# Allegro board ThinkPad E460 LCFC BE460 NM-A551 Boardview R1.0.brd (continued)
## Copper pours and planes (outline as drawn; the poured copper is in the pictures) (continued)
DH_1.35V on BOTTOM (solid shape): 171.44,171.36 171.44,170.61 171.34,170.51 171.34,170.51 170.55,170.51 170.45,170.41 169.87,170.41 169.74,170.53 169.74,171.25 169.92,171.43 171.37,171.43
DH_1.35V on IN3 (solid shape): 178.18,170.99 178.18,170.69 178.09,170.59 177.43,170.59 177.05,170.98 177.05,171.35 177.17,171.47 177.69,171.47
DH_CHG on TOP (solid shape): 229.86,115.37 229.86,114.28 229.63,114.05 229.03,114.05 228.73,114.35 228.73,115.34 228.96,115.58 229.65,115.58
DH_CHG on BOTTOM (solid shape): 230.14,115.63 230.14,114.72 229.55,114.13 228.84,114.13 228.62,114.36 228.62,115.37 229.03,115.78 229.98,115.78
DH_CHG on BOTTOM (solid shape): 223.29,111.4 223.43,111.26 223.43,111.04 223.29,110.9 222.37,110.9 222.13,111.14 221.81,111.14 221.79,111.16 221.03,111.16 221.03,111.32 221.09,111.38 221.8,111.38 221.82,111.4 223.15,111.4
DH_CHG on IN3 (solid shape): 223.77,111.84 223.77,111 223.69,110.91 222.35,110.91 222.25,111.02 222.25,111.51 222.61,111.87 223.74,111.87
DH_CHG on IN3 (solid shape): 229.52,115.26 229.52,114.43 229.32,114.22 229.18,114.22 228.59,113.63 228.5,113.63 227.93,114.2 227.93,114.44 228.9,115.41 229.37,115.41
DL_1.35V on TOP (solid shape): 170.97,175.34 170.97,175.01 170.77,174.82 169.71,174.82 169.54,174.99 169.54,175.3 169.76,175.52 170.78,175.52
DL_1.35V on TOP (solid shape): 179.88,172.13 179.88,171.41 179.78,171.31 179.7,171.31 179.62,171.39 179.62,171.49 178.38,172.73 178.38,172.94 178.54,173.11 178.91,173.11
DL_1.35V on BOTTOM (solid shape): 170.8,175.69 170.8,174.84 170.7,174.74 169.23,174.74 169.1,174.87 169.1,175.58 169.25,175.73 170.77,175.73
DL_1.35V on BOTTOM (solid shape): 179.44,172.46 179.44,172.18 179.3,172.04 179.01,172.04 178.36,172.69 178.36,172.96 178.49,173.09 178.8,173.09
DL_1.35V on IN3 (solid shape): 178.81,173.33 178.81,173.13 179.41,172.52 179.41,172.13 179.34,172.06 179.04,172.06 178.26,172.84 178.22,172.84 178.01,173.06 178.01,173.29 178.31,173.6 178.54,173.6
DL_CHG on TOP (solid shape): 236.83,118.53 236.83,117.48 236.69,117.33 236,117.33 235.86,117.47 235.86,118.39 236.09,118.62 236.74,118.62
DL_CHG on BOTTOM (solid shape): 236.76,118.38 236.76,117.57 236.63,117.44 235.6,117.44 235.52,117.52 235.52,118.39 235.63,118.5 236.64,118.5
DL_CHG on BOTTOM (solid shape): 223.2,113.22 223.2,113.01 222.54,112.35 221.79,112.35 221.78,112.35 221.02,112.35 221.01,112.36 221.01,112.56 221.82,112.56 221.87,112.62 221.98,112.62 222.71,113.35 223.07,113.35
DL_CHG on IN3 (solid shape): 223.49,113.65 223.49,113.09 222.83,112.43 222.14,112.43 222,112.57 222,113.19 222.7,113.89 223.26,113.89
DL_CHG on IN3 (solid shape): 236.75,118.12 236.75,117.45 236.64,117.34 235.56,117.34 235.43,117.47 235.43,118.42 235.47,118.47 235.69,118.47 235.76,118.54 236.33,118.54
DOCK_ID on TOP (solid shape): 277.19,107.94 277.19,106.88 277.01,106.71 277.01,105.88 277.23,105.66 277.23,105.65 278.43,105.65 278.81,106.04 285.88,106.04 286.01,105.91 286.01,103.68 285.72,103.39 283.08,103.39 281.93,104.53 279.15,104.53 278.6,105.09 276.79,105.09 276.03,105.85 276.03,106.61 275.84,106.8 275.68,106.8 275.25,107.24 275.25,107.99 275.4,108.14 276.99,108.14
EC_SMCA on BOTTOM (solid shape): 249.59,125.07 249.59,122.9 249.76,122.73 249.86,122.73 250.2,122.39 250.2,122.11 249.68,121.59 249.68,120.2 249.46,119.98 249.06,119.98 248.86,120.19 248.86,124.97 249.05,125.16 249.51,125.16
EC_SMDA on BOTTOM (solid shape): 250.56,125.39 251.01,125.39 251.22,125.18 251.22,120.21 251.04,120.03 250.55,120.03 250.39,120.19 250.39,122.17 250.4,122.26 250.39,122.35 250.39,122.49 250.03,122.85 249.99,122.85 249.78,123.06 249.78,125.36 249.77,125.37 249.97,125.57 250.38,125.57
EN_1.8VSP on BOTTOM (solid shape): 186.3,175.87 186.3,175.69 186.3,175.69 186.3,175.28 186.58,175 187.95,175 188.21,174.75 188.21,173.96 188.1,173.86 186.54,173.86 186.17,174.22 186.17,174.6 185.59,175.18 184.73,175.18 184.6,175.31 184.6,175.89 184.68,175.97 186.2,175.97
FB_1.35V on TOP (solid shape): 182.89,169.29 182.89,167.3 182.69,167.1 182.41,167.1 182.18,167.33 182.18,168.85 181.71,169.32 181.7,169.32 181.62,169.4 181.62,169.48 181.71,169.58 182.6,169.58
HG_1PH on BOTTOM (solid shape): 70.78,102.49 70.78,101.6 70.52,101.35 69.74,101.35 69.63,101.45 69.63,102.39 69.82,102.59 70.68,102.59
HG_1PH on BOTTOM (solid shape): 74.41,101.4 74.41,100.94 74.22,100.75 73.89,100.75 73.89,100.93 73.66,101.16 72.94,101.16 72.8,101.31 72.8,101.65 72.87,101.72 74.08,101.72
HG_1PH on IN3 (solid shape): 74.08,101.68 74.08,101.33 73.97,101.22 72.96,101.22 72.88,101.3 72.88,101.67 72.75,101.8 72.75,102.38 72.85,102.48 73.29,102.48
HG_A1 on BOTTOM (solid shape): 67.43,72.34 67.43,71.86 67.18,71.61 66.07,71.61 65.79,71.89 65.79,72.29 65.89,72.39 67.37,72.39
HG_A1 on BOTTOM (solid shape): 75.05,74.43 75.05,73.34 74.96,73.24 73.64,73.24 73.54,73.34 73.54,74.46 73.61,74.54 74.95,74.54
HG_B1 on TOP (solid shape): 82.97,53.53 82.97,52.57 82.95,52.57 82.95,51.87 82.91,51.84 82.62,51.84 82.34,52.11 82.34,53.48 82.55,53.69 82.81,53.69
HG_B1 on BOTTOM (solid shape): 84.29,54.38 84.29,54.11 83.38,53.2 83.38,52.69 83.17,52.48 82.53,52.48 82.23,52.78 82.23,53.33 82.99,54.09 82.99,54.41 83.27,54.7 83.97,54.7
HGNDA on TOP (solid shape): 183.65,57.39 183.68,57.36 185.04,57.36 185.04,57.35 185.04,57.21 185,57.17 183.46,57.17 182.96,57.66 181.85,57.66 180.98,56.8 180.98,56.24 180.93,56.19 180.31,56.19 180.18,56.3 180.02,56.34 179.79,56.34 179.61,56.52 179.61,57.28 179.62,57.3 179.62,57.5 179.79,57.66 181.13,57.66 181.72,58.25 182.79,58.25
HGNDA on TOP: 139.37,55.84 139.95,55.84 140.21,55.59 140.21,51.35 140.38,51.17 140.38,50.71 140.39,50.7 140.39,50.45 140.39,50.12 140.24,49.96 139.3,49.96 139.16,50.1 139.16,55.63
HGNDA on IN1: 137.66,57.56 141.1,57.56 142.23,56.43 142.23,52.37 143.52,51.09 143.63,51.09 144.25,50.47 159.63,50.47 160.01,50.08 174.11,50.08 174.74,50.72 178.43,50.72 178.94,51.23 178.94,52.37 178.55,52.75 176.89,52.75 176.77,52.88 176.77,53.6 179.18,56.01 179.18,57.92 179.71,58.45 180.12,58.45 180.47,58.81 182.23,58.81 183.65,57.39 183.65,49.03 182.63,48.01 137.45,48.01 137.03,48.43 137.03,56.93
HGNDB on TOP (solid shape): 183.41,56.96 184.83,56.96 184.84,56.96 185,56.96 185.03,56.93 185.03,56.79 184.98,56.74 183.44,56.74 183.14,56.45 181.87,56.45 181.86,56.46 181.32,56.46 181.29,56.5 181.29,56.88 181.95,57.54 182.84,57.54
HGNDB on TOP: 138.84,51.54 138.82,51.53 138.82,50.12 138.64,49.94 137.65,49.94 137.57,50.02 137.57,55.4 137.94,55.77 138.78,55.77 138.84,55.72
HGNDB on IN2: 142.36,52.37 144.52,50.21 174.11,50.21 174.62,50.72 178.43,50.72 178.94,51.23 178.94,52.37 178.55,52.75 176.89,52.75 176.77,52.88 176.77,55.51 179.71,58.45 180.12,58.45 180.47,58.81 182.23,58.81 183.65,57.39 183.65,49.03 182.63,48.01 136.76,48.01 136.67,48.1 136.67,55.09 137.05,55.47 137.05,57.5 137.36,57.81 141.12,57.81 142.36,56.56
LANGND on TOP: 287.66,89.18 294.77,89.18 295.13,88.82 295.13,88.04 290.68,88.04 290.3,88.42 289.29,88.42 288.73,87.87 288.73,87.8 288.66,87.8 287.65,86.79 286.89,86.79 286.5,86.41 286.5,72.43 289.37,69.57 290.25,69.57 290.76,70.08 296.14,70.08 296.14,69.27 295.61,68.74 284.6,68.74 284.22,69.12 284.22,70.53 276.09,78.66 273.04,78.66 271.26,80.44 267.07,80.44 264.66,82.85 264.66,83.23 264.28,83.61 263.52,83.61 263.14,83.23 258.95,83.23 258.56,83.61 258.56,86.15 259.71,87.3 259.71,89.84 260.34,90.47 262.25,90.47 262.88,89.84 262.88,87.55 263.01,87.42 277.87,87.42 277.87,89.2 280.28,91.61 280.28,92.5 280.66,92.88 283.96,92.88
LANGND on BOTTOM: 260.08,82.85 259.95,82.72 257.42,82.72 257.17,82.98 257.17,85.9 257.42,86.15 258.69,86.15 258.95,85.9 258.95,85.19 259.28,84.86 259.91,84.86 260.08,84.69
LANGND on BOTTOM: 260.33,90.46 262.24,90.46 262.88,89.81 262.88,87.68 263.01,87.55 277.74,87.55 278,87.3 278,85.9 277.74,85.64 263.38,85.64 260.85,88.17 259.98,88.17 259.71,88.44 259.71,89.83
LANGND on BOTTOM: 284.6,68.88 284.22,69.26 284.22,70.53 277.87,76.88 277.87,78.02 280.03,80.18 280.03,84.76 280.41,85.14 282.06,85.14 282.44,85.52 282.44,86.53 282.69,86.79 284.73,86.79 285.62,87.68 285.62,88.95 285.11,89.45 280.54,89.45 280.28,89.71 280.28,92.5 280.66,92.88 283.96,92.88 287.27,89.58 288.3,89.58 288.41,89.69 294.79,89.69 294.98,89.5 294.98,88.1 294.94,88.06 294.94,88.04 290.81,88.04 290.43,88.42 288.03,88.42 286,86.39 286,80.18 282.31,76.5 282.31,74.85 282.82,74.34 285.87,74.34 286.38,73.83 286.38,73.58 286.25,73.45 286.25,72.56 289.43,69.39 289.43,69.13 289.17,68.88
LANGND on GND1: 284.7,68.75 284.22,69.24 284.22,70.51 276.07,78.66 273.02,78.66 271.24,80.44 267.05,80.44 264.66,82.83 264.66,83.21 264.26,83.61 263.54,83.61 263.16,83.23 258.92,83.23 258.56,83.59 258.56,86.17 259.71,87.32 259.71,89.86 260.32,90.47 262.27,90.47 262.99,89.75 262.99,87.55 277.83,87.55 277.83,89.19 277.85,89.2 280.28,91.64 280.28,92.52 280.64,92.88 284.11,92.88 287.8,89.2 296.56,89.2 297.05,88.71 297.05,87.93 290.7,87.93 290.54,88.08 290.48,88.14 290.19,88.44 289.3,88.44 287.65,86.79 286.89,86.79 286.5,86.41 286.5,72.44 289.43,69.52 290.19,69.52 290.7,70.02 296.13,70.02 296.13,70.09 297.05,70.09 297.05,69.24 296.56,68.75
LANGND on IN1: 284.7,68.75 284.22,69.24 284.22,70.51 276.07,78.66 273.02,78.66 271.75,79.93 266.8,79.93 264,82.72 259.44,82.72 258.55,83.61 258.55,86.16 259.71,87.32 259.71,89.86 260.32,90.47 262.27,90.47 262.96,89.78 262.96,87.55 263.08,87.42 277.87,87.42 277.87,89.2 280.28,91.61 280.28,92.5 280.66,92.88 283.96,92.88 284.73,92.12 284.88,92.12 287.8,89.2 296.56,89.2 297.05,88.71 297.05,87.93 290.7,87.93 290.54,88.08 290.48,88.14 290.19,88.44 289.3,88.44 287.65,86.79 286.89,86.79 286.5,86.41 286.5,72.44 289.43,69.52 290.19,69.52 290.7,70.02 296.13,70.02 296.13,70.09 297.05,70.09 297.05,69.24 296.56,68.75 ; 1 cut-out
LANGND on IN2: 284.7,68.75 284.22,69.24 284.22,70.51 276.07,78.66 273.02,78.66 271.75,79.93 266.8,79.93 264,82.72 258.29,82.72 257.42,83.59 257.42,85.54 257.91,86.03 258.42,86.03 259.71,87.32 259.71,89.86 260.32,90.47 262.27,90.47 262.96,89.78 262.96,87.47 263.01,87.42 277.74,87.42 277.87,87.55 277.87,89.2 280.28,91.61 280.28,92.5 280.66,92.88 284.09,92.88 284.85,92.12 284.88,92.12 287.8,89.2 296.56,89.2 297.05,88.71 297.05,87.93 290.7,87.93 290.54,88.08 290.48,88.14 290.19,88.44 289.3,88.44 287.65,86.79 286.89,86.79 286.5,86.41 286.5,72.44 289.43,69.52 290.19,69.52 290.7,70.02 296.13,70.02 296.13,70.09 297.05,70.09 297.05,69.24 296.56,68.75
LANGND on VCC, GND2: 284.7,68.75 284.22,69.24 284.22,70.51 276.07,78.66 273.02,78.66 271.75,79.93 266.8,79.93 264,82.72 258.29,82.72 257.42,83.59 257.42,85.54 257.91,86.03 258.42,86.03 259.71,87.32 259.71,89.86 260.32,90.47 262.27,90.47 262.99,89.75 262.99,87.55 277.83,87.55 277.83,89.19 277.85,89.2 280.28,91.64 280.28,92.52 280.64,92.88 284.11,92.88 287.8,89.2 296.56,89.2 297.05,88.71 297.05,87.93 290.7,87.93 290.54,88.08 290.48,88.14 290.19,88.44 289.3,88.44 287.65,86.79 286.89,86.79 286.5,86.41 286.5,72.44 289.43,69.52 290.19,69.52 290.7,70.02 296.13,70.02 296.13,70.09 297.05,70.09 297.05,69.24 296.56,68.75
LANGND on IN3: 284.7,68.75 284.22,69.24 284.22,70.51 276.07,78.66 273.02,78.66 271.75,79.93 266.8,79.93 264,82.72 258.29,82.72 257.42,83.59 257.42,85.54 257.91,86.03 258.42,86.03 259.71,87.32 259.71,89.86 260.32,90.47 262.27,90.47 262.96,89.78 262.96,87.42 277.61,87.42 277.87,87.68 277.87,89.2 280.28,91.61 280.28,92.5 280.66,92.88 284.11,92.88 287.8,89.2 296.56,89.2 297.05,88.71 297.05,87.93 290.7,87.93 290.54,88.08 290.48,88.14 290.19,88.44 289.3,88.44 287.65,86.79 286.89,86.79 286.5,86.41 286.5,83.97 282.19,83.97 282.01,83.79 282.01,82.22 283.66,80.56 275.71,80.56 275.46,80.31 275.46,80.26 281.35,74.37 285.92,74.37 286.5,73.78 286.5,72.44 289.43,69.52 290.19,69.52 290.7,70.02 296.13,70.02 296.13,70.09 297.05,70.09 297.05,69.24 296.56,68.75 ; 2 cut-outs
LG_1PH on BOTTOM (solid shape): 63.95,102.22 63.95,101.72 63.83,101.59 63.03,101.59 62.99,101.63 62.99,101.8 62.55,102.24 62.55,102.5 62.68,102.63 63.54,102.63
LG_1PH on IN3 (solid shape): 72.82,99.58 73.48,99.58 73.59,99.48 73.59,99.17 73.5,99.08 72.89,99.08 72.73,98.92 72.25,98.92 72.15,99.01 72.15,99.59 72.23,99.68 72.73,99.68
LG_A1 on BOTTOM (solid shape): 63.53,84.68 63.53,83.65 63.38,83.5 62.48,83.5 62.29,83.69 62.29,84.66 62.4,84.77 63.44,84.77
LG_A1 on BOTTOM (solid shape): 63.53,79.14 63.53,78.12 63.38,77.96 62.48,77.96 62.29,78.15 62.29,79.12 62.4,79.23 63.44,79.23
LG_A1 on BOTTOM (solid shape): 64.45,73.4 64.45,72.68 64.61,72.51 64.61,71.92 64.54,71.85 64.28,71.85 63.91,72.22 63.91,73.13 63.87,73.18 63.87,73.42 64.01,73.56 64.28,73.56
LG_A1 on IN3 (solid shape): 63.52,84.73 63.52,78.88 63.39,78.75 62.53,78.75 62.38,78.9 62.38,84.71 62.52,84.85 63.39,84.85
LG_A1 on IN3 (solid shape): 64.85,74.19 64.85,73.94 64.41,73.51 64.41,72.57 64.28,72.45 63.85,72.45 63.72,72.58 63.72,73.91 63.84,74.03 63.84,74.29 63.86,74.32 64.72,74.32
LG_B1 on TOP (solid shape): 88.76,51.53 91.42,51.53 91.51,51.44 91.51,50.48 91.44,50.4 85.16,50.4 85.01,50.56 85.01,51.29 85.24,51.52 87.44,51.52 87.45,51.54 87.45,51.58 87.16,51.87 84.16,51.87 84.13,51.9 84.13,52.27 84.71,52.84 87.45,52.84
LG_B1 on BOTTOM (solid shape): 86.3,51.45 86.3,50.41 86.17,50.28 85.29,50.28 85.04,50.53 85.04,51.39 85.16,51.52 86.24,51.52
LG_B1 on BOTTOM (solid shape): 92.27,51.48 92.27,50.44 92.14,50.3 90.96,50.3 90.88,50.38 90.88,51.39 91.04,51.54 92.21,51.54
LX_1.35V on TOP (solid shape): 168.59,172.57 168.59,171.5 168.41,171.32 165.82,171.32 165.67,171.47 165.67,172.63 165.86,172.81 168.35,172.81
LX_1.35V on TOP (solid shape): 178.09,173.54 178.09,172.69 179.54,171.25 179.54,171.03 179.47,170.96 178.63,170.96 177.83,171.76 177.27,171.76 177.05,171.97 177.05,173.71 177.22,173.88 177.76,173.88
LX_1.35V on BOTTOM (solid shape): 166,174.7 166,174.7 166.13,174.56 166.14,174.56 166.23,174.46 169.74,174.46 169.99,174.22 169.99,171.85 169.8,171.65 169.66,171.65 169.66,171.62 169.54,171.5 169.54,170.48 169.41,170.35 166.77,170.35 166.41,170 166.41,169.19 166.18,168.95 162.52,168.95 162.27,169.2 162.27,175.67 162.56,175.96 164.74,175.96
LX_CHG on TOP (solid shape): 233.52,115.27 233.52,114.09 233.34,113.91 231.74,113.91 231.51,114.13 231.51,114.82 232.11,115.42 233.38,115.42
LX_CHG on BOTTOM (solid shape): 222.3,110.72 223.63,110.72 223.73,110.62 224.71,110.62 224.8,110.53 224.8,109.7 224.77,109.66 222.96,109.66 221.9,110.71 221.86,110.71 221.82,110.75 221.05,110.75 221.03,110.77 221.03,110.92 221.07,110.97 221.81,110.97 221.84,110.99 222.03,110.99
LX_CHG on BOTTOM (solid shape): 236.4,117.05 236.4,114.02 235.7,113.31 235.7,104.7 235.25,104.25 230.04,104.25 229.98,104.19 229.61,104.19 229.1,104.69 229.1,113.21 230.37,114.48 230.37,115.73 230.52,115.88 231.85,115.88 231.93,115.96 232,115.96 232.71,116.67 232.71,116.74 233.25,117.28 236.18,117.28
LX_CHG on IN3 (solid shape): 232.9,114.37 232.9,113.98 232.67,113.75 232.22,113.75 232.08,113.6 231.67,114.01 231.67,114.49 231.76,114.58 232.69,114.58
LX_CHG on IN3 (solid shape): 224.6,110.03 224.56,110 223.57,110 223.54,110.03 222.6,110.03 222.4,110.24 222.4,110.57 222.54,110.71 223.49,110.71 223.5,110.72 223.98,110.72 224.04,110.77 224.6,110.77
P2 on BOTTOM (solid shape): 272.01,108.22 272.01,107.8 272.78,107.03 273.7,107.03 273.83,106.9 273.83,104.68 273.54,104.39 273.42,104.39 272.97,103.94 272.97,103.19 272.79,103.01 272.13,103.01 272.01,103.13 272.01,103.89 272.2,104.07 272.2,105.05 271.98,105.27 270.65,105.27 270.55,105.38 270.55,108.16 270.83,108.45 271.78,108.45
P3 on BOTTOM (solid shape): 267.71,107.75 270.15,107.75 270.33,107.57 270.33,101.7 270.12,101.49 266.57,101.49 266.41,101.65 266.41,101.85 266.42,101.85 266.42,102.01 266.41,102.01 266.41,103.38 266.06,103.74 263.88,103.74 263.55,104.07 263.55,108.68 263.72,108.85 266.61,108.85
RJ45_GND on BOTTOM: 266.44,81.45 270.12,81.45 270.13,81.45 272.79,81.45 273.42,80.82 277.74,80.82 278.38,81.45 278.38,87.55 279.9,89.07 282.95,89.07 283.2,88.82 283.2,87.17 283.08,87.04 280.28,87.04 279.77,86.53 279.77,80.44 278.12,78.79 273.04,78.79 272.39,79.44 272.17,79.44 272.15,79.42 266.57,79.42 266.06,79.93 266.06,81.07
SPK_L1-_CON on TOP: 190.2,66.4 190.89,66.4 191.01,66.28 191.01,65.21 189.49,63.68 188.86,63.68 188.6,63.43 188.6,62.29 188.45,62.14 187.74,62.14 187.61,62.26 187.61,63.94 188.27,64.6 189.16,64.6 190.13,65.56 190.13,66.33
SPK_L1-_CON on BOTTOM: 239.88,99.09 239.88,97.06 240.27,96.68 241.41,96.68 241.54,96.81 241.54,99.09 241.41,99.22 240.01,99.22
SPK_L1-_CON on IN3: 188.45,64.68 189.85,64.68 190.1,64.42 190.1,63.79 190.61,63.28 190.61,62.39 190.35,62.14 188.45,62.14 188.2,62.39 188.2,64.42
SPK_L2+_CON on TOP: 191.29,66.38 191.85,66.38 191.98,66.25 191.98,64.19 191.04,63.25 191.04,62.34 190.79,62.08 189.85,62.08 189.69,62.24 189.69,63.63 191.22,65.16 191.22,66.3
SPK_L2+_CON on BOTTOM: 238.61,99.22 239.5,99.22 239.63,99.09 239.63,96.93 239.76,96.81 239.76,95.16 239.5,94.9 238.61,94.9 238.49,95.03 238.49,99.09
SPK_L2+_CON on IN3: 190.74,65.82 191.88,65.82 192.01,65.69 192.01,64.04 191.88,63.91 190.74,63.91 190.61,64.04 190.61,65.69
SPK_R1-_CON on TOP: 189.24,66.45 189.8,66.45 189.9,66.35 189.9,65.59 189.08,64.78 188.17,64.78 187.38,63.99 187.38,62.47 187.18,62.26 186.47,62.26 186.37,62.36 186.37,64.19 187.66,65.49 188.93,65.49 189.14,65.69 189.14,66.35
SPK_R1-_CON on BOTTOM: 237.34,99.22 238.11,99.22 238.23,99.09 238.23,96.17 237.98,95.92 236.84,95.92 236.71,96.04 236.71,96.68 237.22,97.19 237.22,99.09
SPK_R1-_CON on IN3: 189.72,65.06 188.2,65.06 187.81,64.68 187.81,63.28 187.56,63.02 186.42,63.02 186.29,63.15 186.29,66.33 186.54,66.58 189.85,66.58 189.97,66.45 189.97,65.31
SPK_R2+_CON on TOP: 188.73,66.55 186.93,66.55 183.8,63.43 183.8,62.49 183.95,62.34 184.89,62.34 185.45,62.9 185.45,63.51 187.64,65.69 188.75,65.69 188.88,65.82 188.88,66.4
SPK_R2+_CON on BOTTOM: 234.68,99.22 236.84,99.22 236.96,99.09 236.96,97.7 236.71,97.44 234.68,97.44 234.55,97.57 234.55,99.09
SPK_R2+_CON on IN3: 185.27,63.28 185.15,63.15 184,63.15 183.88,63.28 183.88,64.8 184,64.93 185.15,64.93 185.27,64.8
SW_1.00VS on TOP (solid shape): 144.28,173.47 144.28,171.56 144.1,171.38 141.98,171.38 141.58,171.77 141.58,173.32 141.85,173.59 144.16,173.59
SW_1.00VS on BOTTOM (solid shape): 145.67,175.56 145.67,175.31 147.22,173.76 148.28,172.7 148.28,170.68 148.25,170.65 147.44,170.65 147.43,170.65 147.17,170.9 146.24,170.9 146.1,171.04 140.08,171.04 139.85,171.27 139.85,173.85 139.01,174.7 139.01,175.61 139.23,175.84 145.39,175.84
SW_1PH on TOP (solid shape): 68.69,103.11 68.69,101.74 68.44,101.49 66.98,101.49 66.84,101.63 66.84,102.89 67.23,103.28 68.52,103.28
SW_1PH on BOTTOM (solid shape): 72.75,100.93 73.48,100.93 73.85,100.56 74.26,100.56 74.3,100.52 74.3,100.25 74.29,100.24 73.46,100.24 73.29,100.4 71.21,100.4 71.02,100.59 71.02,101.16 71.21,101.36 72.32,101.36
SW_1PH on BOTTOM (solid shape): 68.67,109.53 68.67,107.02 68.24,106.59 67.11,106.59 67.07,106.55 67.07,105.9 68.14,105.9 68.3,105.73 68.56,105.73 69.39,104.91 69.39,101.44 68.95,101 67.79,101 67.45,100.66 67.45,99.53 67.03,99.11 64.65,99.11 64.23,99.53 64.23,102.2 63.86,102.57 63.86,108.24 65.42,109.8 68.4,109.8
SW_1PH on IN3 (solid shape): 68.75,102.76 68.75,102.51 68.4,102.17 68.2,102.17 67.83,102.54 67.51,102.54 67.34,102.71 67.34,103.06 67.43,103.15 68.36,103.15
SW_A1 on TOP (solid shape): 67.85,74.41 67.85,73.75 67.67,73.57 67.2,73.57 67.18,73.59 65.2,73.59 65.09,73.69 65.09,74.33 65.28,74.52 67.74,74.52
SW_A1 on BOTTOM (solid shape): 69.22,83.82 69.22,81.66 71.12,79.76 72.42,79.76 72.64,79.55 72.64,78.3 72.76,78.18 73.65,78.18 73.78,78.3 73.78,79.62 74.21,80.06 74.21,80.07 76.07,80.07 76.22,79.92 76.22,76.62 74.46,74.86 73.33,74.86 72.92,74.45 72.92,73.34 72.78,73.21 69.07,73.21 68.58,72.72 66.96,72.72 66.95,72.73 65.84,72.73 65.6,72.49 65.6,71.86 65.54,71.8 65.41,71.8 65.28,71.94 65.28,72.46 65.25,72.49 65.25,73.21 64.66,73.8 64.66,73.8 64.21,74.25 64.21,83.99 64.68,84.46 68.58,84.46
SW_B1 on TOP (solid shape): 85.32,55.59 85.32,54.15 84.68,53.51 84.02,53.51 83.46,52.95 83.46,51.91 83.41,51.86 83.18,51.86 83.13,51.91 83.13,53.28 83.53,53.69 83.53,54.41 83.54,54.42 83.54,55.56 83.65,55.67 85.24,55.67
SW_B1 on BOTTOM (solid shape): 89.37,62.82 89.37,61.56 90.1,61.56 90.1,62.77 90.55,63.22 93.78,63.22 94.07,62.93 94.07,59.04 96.57,56.54 96.57,54.6 96.8,54.37 97.71,54.37 97.89,54.19 97.89,53.39 97.78,53.27 96.67,53.27 96.57,53.16 96.57,52.13 96.42,51.99 85.33,51.99 84.9,52.41 84.9,54.47 84.41,54.97 83.26,54.97 83.03,55.2 83.03,58.87 86.26,62.1 86.26,63.12 86.44,63.3 88.88,63.3
VGA_LGATE1 on TOP (solid shape): 94.3,163.81 94.3,162.8 94.15,162.65 93.19,162.65 92.99,162.85 92.99,163.69 93.22,163.92 94.18,163.92
VGA_LGATE1 on BOTTOM (solid shape): 100.04,164.63 100.04,163.47 99.89,163.32 99.89,163.32 99.22,162.65 99.14,162.65 98.81,162.97 98.81,163.87 99.65,164.7 99.97,164.7
VGA_LGATE1 on BOTTOM (solid shape): 114.15,170.82 114.74,170.82 114.77,170.8 114.77,170.61 114.75,170.6 114.14,170.6 114.12,170.57 113.53,170.57 113.47,170.52 113.47,170.51 112.9,169.94 112.34,169.94 112.2,170.07 112.2,170.28 112.39,170.48 112.53,170.48 112.9,170.85 114.13,170.85
VGA_LGATE1 on IN3 (solid shape): 100.05,164.52 100.05,163.75 99.88,163.58 99.72,163.58 98.89,162.75 93.24,162.75 93.1,162.89 93.1,163.76 93.23,163.9 98.34,163.9 98.35,163.91 98.84,163.91 99.63,164.7 99.87,164.7
VGA_LGATE1 on IN3 (solid shape): 113.26,170.72 113.26,170.26 112.52,169.52 110.53,169.52 110.41,169.64 110.41,170.39 110.47,170.44 110.81,170.44 110.89,170.36 112.3,170.36 112.4,170.45 112.54,170.45 112.89,170.8 113.18,170.8
VGA_LGATE2 on TOP (solid shape): 98.74,169.23 98.74,168.26 98.5,168.02 97.55,168.02 97.35,168.22 97.35,169.13 97.55,169.33 98.64,169.33
VGA_LGATE2 on BOTTOM (solid shape): 92.83,169.06 92.83,168.11 92.71,168 91.69,168 91.55,168.13 91.55,169.09 91.71,169.26 92.63,169.26
VGA_LGATE2 on BOTTOM (solid shape): 113.04,172.05 114.14,172.05 114.17,172.02 114.75,172.02 114.81,171.96 114.81,171.84 114.78,171.81 114.15,171.81 114.12,171.78 112.03,171.78 111.75,172.06 111.75,172.44 111.91,172.59 112.49,172.59
VGA_LGATE2 on IN3 (solid shape): 98.75,169.09 98.75,168.26 98.59,168.1 91.6,168.1 91.49,168.22 91.49,169.1 91.66,169.27 98.57,169.27
VGA_LGATE2 on IN3 (solid shape): 111.35,172.68 112.04,172.68 112.27,172.45 112.65,172.45 112.89,172.21 112.89,171.94 112.79,171.84 111.38,171.84 111.31,171.76 111.04,171.76 110.9,171.91 110.9,172.7 110.97,172.78 111.25,172.78
VGA_PHASE1 on TOP (solid shape): 101.46,162.37 101.46,158.66 99.97,157.17 90.38,157.17 89.86,157.69 89.86,159.46 90.95,160.55 90.95,161.04 91.48,161.57 93.1,161.57 93.72,162.19 99.02,162.19 99.53,162.69 101.15,162.69
VGA_PHASE1 on BOTTOM (solid shape): 114.16,170.43 114.78,170.43 114.8,170.4 114.8,170.25 114.77,170.21 113.94,170.21 113.07,169.33 112.44,169.33 112.16,169.06 112.16,168.81 111.81,168.45 111.56,168.45 111.56,168.45 109.77,168.45 109.64,168.58 109.64,169.35 110.09,169.8 113.05,169.8 113.69,170.45 114.14,170.45
VGA_PHASE1 on BOTTOM (solid shape): 92.89,163.9 92.89,162.81 93.18,162.52 93.8,162.52 93.97,162.36 99.25,162.36 99.25,162.36 99.46,162.36 99.56,162.46 102.35,162.46 102.72,162.1 102.72,158.69 101.18,157.16 93.77,157.16 93.32,157.61 89.54,157.61 89.07,158.08 89.07,160.75 89.35,161.03 90.48,161.03 90.54,161.09 90.54,161.57 90.53,161.58 90.53,161.86 90.42,161.97 89.27,161.97 89.07,162.17 89.07,164.29 89.35,164.57 92.22,164.57
VGA_PHASE1 on IN3 (solid shape): 112.1,169.07 112.1,168.8 111.93,168.63 111.57,168.63 111.14,168.19 110.83,168.19 110.45,168.57 110.78,168.9 110.82,168.9 111.08,169.16 112.02,169.16
VGA_PHASE1 on IN3 (solid shape): 100.02,162.52 100.02,162.24 99.85,162.07 99.85,161.73 99.91,161.67 99.91,161.47 99.78,161.34 99.27,161.34 99.16,161.45 99.16,162.56 99.33,162.73 99.81,162.73
VGA_PHASE2 on TOP (solid shape): 98.23,174.31 98.23,170.31 97.7,169.77 92.62,169.77 92.3,169.45 90.96,169.45 90.44,169.97 90.44,170.44 90.26,170.63 87.73,170.63 87.24,171.12 87.24,172.67 89.23,174.67 97.88,174.67
VGA_PHASE2 on BOTTOM (solid shape): 113.67,172.45 113.69,172.44 114.08,172.44 114.1,172.42 114.79,172.42 114.79,172.41 114.79,172.23 114.76,172.19 114.14,172.19 114.11,172.17 113.16,172.17 112.45,172.89 110.73,172.89 110.5,173.12 110.5,173.69 110.6,173.79 112.34,173.79
VGA_PHASE2 on BOTTOM (solid shape): 97.56,174.28 97.56,173.89 97.94,173.51 99.08,173.51 99.31,173.28 99.31,170.26 99.31,170.26 99.31,170.12 99.07,169.89 98.07,169.89 97.68,169.5 91.6,169.5 91.3,169.21 91.3,168.17 91.11,167.98 89.72,167.98 89.41,167.67 89.41,167.23 88.46,166.27 86.99,166.27 86.36,166.9 86.36,168.95 86.82,169.41 86.83,169.4 88.1,169.4 88.1,170.01 88,170.11 86.73,170.11 86.36,170.47 86.36,173.07 89,175.71 96.14,175.71
VGA_PHASE2 on IN3 (solid shape): 92.64,174.02 92.64,173.43 92.21,173 91.83,173 91.52,173.32 91.31,173.32 91.12,173.51 91.12,173.7 91.26,173.83 91.56,173.83 91.91,174.18 92.48,174.18
VGA_PHASE2 on IN3 (solid shape): 112.25,173.62 112.55,173.62 112.85,173.32 112.85,173.03 112.77,172.95 112.46,172.95 112.35,173.07 111.81,173.07 111.46,173.41 111.37,173.41 111.24,173.54 111.24,174.14 111.28,174.18 111.69,174.18
VGA_UGATE1 on BOTTOM (solid shape): 102.82,163.79 102.82,163.2 102.29,162.67 101.19,162.67 100.97,162.89 100.97,163.32 101.61,163.96 102.65,163.96
VGA_UGATE1 on BOTTOM (solid shape): 114.8,169.99 114.8,169.83 114.77,169.8 114.14,169.8 113.96,169.63 113.96,169.19 113.32,168.55 112.52,168.55 112.39,168.67 112.39,168.91 112.55,169.07 113.11,169.07 113.76,169.73 114.06,170.02 114.76,170.02
VGA_UGATE1 on IN3 (solid shape): 103.18,163.92 103.18,163.43 103.06,163.31 101.83,163.31 101.68,163.46 101.68,163.75 101.83,163.91 102.45,163.91 102.61,164.06 103.04,164.06
VGA_UGATE1 on IN3 (solid shape): 113.58,169.07 113.58,168.69 113.44,168.55 113.27,168.55 112.81,168.09 112.42,168.09 112.18,168.32 112.18,168.52 112.38,168.71 112.38,168.92 112.59,169.13 113.14,169.13 113.19,169.19 113.46,169.19
VGA_UGATE2 on BOTTOM (solid shape): 99.39,174.9 99.39,174.29 98.87,173.77 97.9,173.77 97.78,173.89 97.78,174.78 97.99,174.99 99.31,174.99
VGA_UGATE2 on BOTTOM (solid shape): 113.85,174.08 113.85,173.09 114.13,172.81 114.78,172.81 114.78,172.62 114.76,172.6 113.79,172.6 113.78,172.59 113.39,172.98 112.35,174.03 112.35,174.29 112.47,174.41 113.52,174.41
VGA_UGATE2 on IN3 (solid shape): 99.95,175.04 99.95,174.51 99.83,174.39 98.34,174.39 98.22,174.51 98.22,174.93 98.42,175.14 99.84,175.14
VMB on BOTTOM (solid shape): 265.19,114.42 265.19,109.36 264.84,109.01 262.18,109.01 262.15,109.04 261.71,109.04 261.61,109.14 261.61,109.65 261.42,109.84 260.63,109.84 260.37,110.1 260.37,112 260.83,112.45 260.83,114.75 261.49,115.41 264.2,115.41
VMB2 on TOP (solid shape): 251.24,117.25 258.41,117.25 259.28,116.38 259.28,112.23 259,111.96 246.05,111.96 245.04,112.96 245.04,114.91 242.72,117.24 242.72,118.84 243.02,119.15 243.05,119.12 243.71,119.12 243.73,119.15 244.68,119.15 245.57,120.03 248.45,120.03
VMB2 on BOTTOM (solid shape): 248.62,125.11 248.62,119.92 249.23,119.31 251.8,119.31 253.2,117.92 254.26,117.92 255.6,116.58 255.6,116.55 256.03,116.11 259.9,116.11 260.37,115.64 260.37,112.74 259.9,112.27 256.06,112.27 255.24,111.46 246.05,111.46 245.42,112.08 245.42,124.93 245.68,125.19 248.54,125.19
VSYSTEM on BOTTOM (solid shape): 277.42,108.04 277.42,105.29 277.29,105.16 277.29,102.21 277.08,102 274.19,102 274.06,102.13 274.06,107.85 273.61,108.3 273.61,108.98 273.78,109.15 276.31,109.15
N18669 on BOTTOM (solid shape): 111.79,168.09 111.79,167.29 111.67,167.17 109.79,167.17 109.53,166.9 108.55,166.9 108.4,167.05 108.4,167.43 109.21,168.24 111.64,168.24
N18705 on BOTTOM (solid shape): 114.8,169.56 114.8,169.32 114.73,169.25 114.73,168.79 113.15,167.21 112.33,167.21 112.24,167.3 112.24,168.15 112.43,168.34 113.32,168.34 114.15,169.17 114.15,169.53 114.23,169.61 114.76,169.61
N22144 on BOTTOM (solid shape): 112.27,175.36 112.27,174.46 112.18,174.37 111.86,174.37 111.85,174.36 110.24,174.36 110.03,174.57 110.03,174.93 109.91,175.05 108.91,175.05 108.83,175.13 108.83,175.43 108.97,175.57 112.06,175.57
N22186 on BOTTOM (solid shape): 114.7,175.35 114.7,173.39 114.8,173.29 114.8,173.08 114.73,173.01 114.2,173.01 113.99,173.22 113.99,174.14 113.57,174.55 112.89,174.55 112.82,174.62 112.82,175.41 112.88,175.46 114.6,175.46
N34928 on BOTTOM (solid shape): 114.78,171.57 114.78,171.45 114.72,171.39 112.31,171.39 112.06,171.14 111.09,171.14 111.02,171.22 111.02,171.52 111.12,171.62 114.72,171.62
N15168718 on TOP (solid shape): 176.82,173.68 176.82,171.62 176.71,171.51 174.58,171.51 174.34,171.75 174.34,173.71 174.47,173.83 175.88,173.83 175.88,173.84 176.66,173.84
N15269244 on BOTTOM (solid shape): 194.05,175.81 194.05,175.26 193.92,175.13 192.77,175.13 192.41,174.77 192.41,173.14 192.4,173.12 191.99,173.12 191.92,173.2 191.92,173.24 191.29,173.86 190.54,173.86 190.44,173.96 190.44,174.15 190.93,174.63 190.93,175.32 191.49,175.89 193.97,175.89
N16794121 on BOTTOM (solid shape): 263.22,108.68 263.22,103.79 262.91,103.48 262.91,99.58 262.37,99.04 258.05,99.04 257.86,99.23 257.86,99.77 258.34,100.25 258.34,100.55 257.85,101.04 257.85,103.04 259.15,104.33 259.15,107.95 259.95,108.75 263.15,108.75
N16794165 on BOTTOM (solid shape): 222.87,109.49 223.06,109.49 223.15,109.4 223.15,108.62 223,108.47 222.53,108.47 220.95,110.05 220.95,110.44 221.09,110.57 221.78,110.57
N16794166 on BOTTOM (solid shape): 228.59,106.45 228.59,103.82 228.16,103.39 226.61,103.39 226.16,103.83 226.16,104.47 225.73,104.9 225.04,104.9 224.85,105.09 224.85,105.61 224.87,105.75 224.85,105.88 224.85,106.7 224.91,106.76 228.28,106.76
N16794173 on BOTTOM (solid shape): 227.26,111.68 227.26,109.82 227.05,109.61 225.23,109.61 224.99,109.85 224.99,111.58 225.26,111.85 227.09,111.85
N16794279 on BOTTOM (solid shape): 272.05,104.97 272.05,104.2 271.83,103.98 271.83,103.02 271.79,102.97 270.87,102.97 270.75,103.09 270.75,105.05 270.83,105.13 271.9,105.13
N16901916 on TOP (solid shape): 92.62,163.39 92.62,162.05 92.48,161.91 91.49,161.91 91.2,161.62 90.62,161.62 90.47,161.77 90.47,162.25 90.57,162.35 90.92,162.35 91.32,162.76 91.32,163.5 91.57,163.76 92.26,163.76
N16902103 on TOP (solid shape): 90.22,170.01 90.22,169.56 90.53,169.25 91.19,169.25 91.2,169.26 91.32,169.26 91.43,169.15 91.43,168.65 91.28,168.51 88.77,168.51 88.63,168.64 88.63,169.93 88.95,170.25 89.99,170.25
N16922835 on TOP (solid shape): 234.79,117.34 234.79,116.02 234.69,115.92 234.46,115.92 234.43,115.95 234.03,115.95 234.03,115.93 232.06,115.93 231.97,116.02 231.97,116.98 232.45,117.46 234.68,117.46
N16954250 on BOTTOM (solid shape): 252.67,124.95 252.67,120.19 252.52,120.04 251.96,120.04 251.57,120.43 251.57,124.8 251.8,125.03 252.59,125.03
N26325477 on TOP (solid shape): 76.19,69.13 76.19,66.34 76.07,66.21 75.81,66.21 75.73,66.14 72.02,66.14 71.87,66.28 71.87,69.13 72.13,69.39 75.94,69.39
N26325477 on BOTTOM (solid shape): 75.51,72.36 75.51,71.4 75.54,71.37 75.54,71.37 76.01,70.91 76.01,69.4 76.32,69.1 76.79,69.1 77.08,68.81 77.08,66.01 76.91,65.84 76.22,65.84 75.77,66.29 71.24,66.29 68.9,68.63 68.9,72.73 69.12,72.95 74.92,72.95
N26386889 on TOP (solid shape): 69.26,75.79 69.26,75 69.04,74.79 65.15,74.79 65.03,74.9 65.03,75.5 65.24,75.71 66.03,75.71 66.24,75.92 69.13,75.92
N31349437 on BOTTOM (solid shape): 68.7,72.38 68.7,70.27 68.6,70.16 68,70.16 67.68,70.48 67.68,72.28 67.88,72.47 68.61,72.47
N31349441 on BOTTOM (solid shape): 67.3,71.12 67.3,70.05 67.1,69.85 67.1,69.29 66.87,69.06 66.26,69.06 66.13,69.19 66.13,69.76 65.78,70.11 65.78,70.56 65.84,70.61 66,70.61 66.58,71.19 67.22,71.19
N31382737 on BOTTOM (solid shape): 80.68,64.31 80.68,61.28 80.66,61.26 80.66,61.04 81.6,60.11 81.6,59.18 81.91,58.86 82.47,58.86 82.72,58.61 82.72,54.26 82.17,53.71 77.72,53.71 77.34,54.09 77.34,55.8 77.21,55.93 77.2,55.93 76.18,56.94 76.18,58.8 76.83,59.45 76.83,62.42 76.43,62.81 76.43,64.4 76.54,64.51 80.48,64.51
N31383366 on BOTTOM (solid shape): 97.76,52.98 99.18,52.98 99.31,52.85 99.31,51.38 99.14,51.21 97.19,51.21 96.81,51.6 96.81,52.93 96.86,52.98 97.76,52.98
N31383897 on TOP (solid shape): 83.14,55.32 83.14,54.32 82.88,54.05 82.54,54.05 82.12,53.62 82.12,52.96 81.94,52.78 81.2,52.78 81.02,52.97 81.02,55.29 81.25,55.52 81.93,55.52 81.94,55.53 82.93,55.53
N31383905 on TOP (solid shape): 82.1,52.21 82.1,51.12 82.59,50.63 82.81,50.63 82.95,50.48 82.95,50.07 82.9,50.01 82.58,50.01 82.58,50.01 81.94,50.01 81.1,50.85 81.1,52.27 81.17,52.33 81.98,52.33
N31389989 on TOP (solid shape): 75.5,98.01 75.5,96.92 75.14,96.56 73.06,96.56 72.54,97.09 71.8,97.09 71.63,97.26 71.63,98.4 71.74,98.51 75,98.51
N31389989 on BOTTOM (solid shape): 72.5,98.8 76.32,98.8 76.59,98.52 76.59,96.57 76.49,96.47 74.77,96.47 74.61,96.64 71.41,96.64 71.08,96.3 68.74,96.3 68.61,96.43 68.61,97.05 67.88,97.78 67.88,98.2 67.59,98.49 67.59,100.43 67.99,100.82 70.47,100.82
N31390138 on TOP (solid shape): 67.02,101.07 69.3,101.07 69.41,100.96 69.41,100.1 69.28,99.96 66.59,99.96 66.11,100.44 66.11,101.14 66.31,101.33 66.76,101.33
N31390261 on BOTTOM (solid shape): 74.1,103.49 74.1,103.26 74.11,103.25 74.11,102.09 73.94,101.92 72.83,101.92 72.53,101.61 71.24,101.61 70.95,101.9 70.95,102.49 71.04,102.57 72.59,102.57 73.61,103.6 73.99,103.6
N31390277 on BOTTOM (solid shape): 75.46,102.84 76.32,102.84 76.52,102.64 76.52,101.81 76.21,101.49 76.21,100.83 76.11,100.73 75.69,100.73 75.62,100.8 75.62,101.17 75.23,101.55 74.67,101.55 74.31,101.92 74.31,102.76 74.4,102.85 75.46,102.85
N36436059 on TOP (solid shape): 169.89,174.37 169.89,173.33 169.67,173.1 167.13,173.1 167.01,173.22 167.01,174.34 167.37,174.7 169.56,174.7
N36436199 on TOP (solid shape): 177.45,170.39 178.65,170.39 178.67,170.38 179.42,170.38 179.42,170.21 179.37,170.16 178.66,170.16 178.63,170.14 174.63,170.14 174.36,170.4 174.36,171.06 174.5,171.2 176.64,171.2
N48440766 on TOP (solid shape): 145.18,170.9 145.18,169.72 145.01,169.55 142.28,169.55 142.11,169.72 142.11,170.99 142.17,171.05 145.03,171.05
N48440814 on TOP (solid shape): 145.43,174.76 145.43,172.45 145.26,172.27 144.68,172.27 144.45,172.5 144.45,173.8 144.42,173.83 143.76,173.83 143.66,173.93 143.66,174.77 143.74,174.86 144.58,174.86 144.59,174.87 145.32,174.87
N56243451 on BOTTOM (solid shape): 279.85,108.17 279.85,101.21 279.65,101.01 279.65,101.01 278.63,101.01 277.54,102.11 277.54,105.08 277.7,105.24 277.7,108.08 277.89,108.27 279.75,108.27
N56799483 on IN1: 266.66,96.91 275.57,96.91 275.75,96.73 275.75,94.32 275.32,93.89 266.35,93.89 265.89,94.34 265.89,96.15
N57722199 on BOTTOM: 280.58,124.57 283.04,124.57 283.39,124.21 283.39,123.37 283.72,123.04 284.72,123.04 285.12,122.64 285.12,120.1 285.02,120 282.42,120 282.2,119.78 280.76,119.78 280.27,120.28 280.27,124.26
N57774513 on BOTTOM: 249.54,91.47 249.66,91.35 249.66,89.57 249.54,89.44 247.25,89.44 247.25,89.44 246.89,89.44 246.75,89.58 246.75,91.36 246.88,91.49 247.62,91.49 247.63,91.47
N57774513 on BOTTOM: 245.35,84.61 248.65,84.61 248.77,84.49 248.77,82.71 248.65,82.58 244.56,82.58 244.38,82.76 244.38,83.7 244.51,83.83 245.07,83.83 245.22,83.98 245.22,84.49
N57774513 on IN1: 243.95,90.58 243.95,89.31 244.33,88.93 244.33,83.47 244.58,83.22 248.77,83.22 249.28,83.73 249.28,90.58 249.03,90.84 248.01,90.84 246.87,89.69 245.47,89.69 244.46,90.71 244.08,90.71
N58636580 on TOP: 74.53,161.45 74.4,161.32 72.37,161.32 71.86,160.81 70.59,160.81 70.48,160.93 70.48,161.32 70.48,161.32 71.02,161.32 71.05,161.34 71.05,161.83 71.02,161.85 70.51,161.85 70.48,161.88 70.48,162.94 70.68,163.14 74.29,163.14 74.53,162.9
N59727917 on TOP (solid shape): 269.49,112.82 269.49,111.25 268.5,110.27 267.62,110.27 267.26,109.9 266.5,109.9 266.35,110.05 266.35,111.17 266.47,111.29 267.22,111.29 267.58,111.65 267.58,112.82 267.96,113.2 269.11,113.2
N60939795 on BOTTOM (solid shape): 217.04,169.17 217.04,168.55 217.23,168.36 217.23,167.35 217.16,167.28 214.85,167.28 214.83,167.3 214.24,167.3 214.19,167.34 214.19,167.54 214.24,167.58 214.95,167.58 215.17,167.8 215.17,168.55 215.87,169.25 216.96,169.25
N63300161 on BOTTOM (solid shape): 198.6,168.17 198.6,166.72 198.51,166.63 197.49,166.63 197.49,166.63 196.32,166.63 196.16,166.8 196.16,168.02 196.41,168.27 198.51,168.27
N63300165 on TOP (solid shape): 198.43,167.87 200.44,167.87 200.44,167.87 201.29,167.87 201.52,167.64 202.94,167.64 203.11,167.47 203.11,166.53 202.89,166.31 197.78,166.31 197.46,166.63 197.46,167.74 197.61,167.89 198.4,167.89
N66563319 on TOP: 146.58,162.91 146.58,164.41 147.06,164.89 147.57,164.89 147.82,164.64 147.82,162.61 148.14,162.29 148.72,162.29 148.89,162.12 148.89,161.01 148.76,160.88 148.05,160.88 147.85,161.08 147.85,161.69 147.64,161.9 147.59,161.9
N67109924 on BOTTOM (solid shape): 220.79,172.72 220.79,169.59 220.57,169.36 219.47,169.36 219.3,169.54 219.3,172.69 219.47,172.87 220.64,172.87
N68275593 on TOP: 139.95,161.72 141.95,161.72 142.92,162.68 144.11,162.68 144.26,162.83 144.26,163.37 144.39,163.5 145.23,163.5 145.41,163.32 145.41,162.1 145.33,162.02 144.59,162.02 144.44,161.87 144.44,160.52 144.19,160.27 143.88,160.27 143.58,160.57 139.95,160.57 139.82,160.7 139.82,161.59

Small or netless copper shapes (teardrops, artwork), in the pictures only: 12 on TOP, 59 on BOTTOM, 107 on IN2, 10 on IN3

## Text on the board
User.Comments: RUBY | 2015-07-27 | BE460 | NM-A551 | 2016-07-27 | 1.0
Ref Des/Silkscreen Top: M2X3.5 | M2X5 | LED
User.39: FIGURE | SIZE | 8.0 | 10.0 | 22.0 | 28.0 | 30.0 | 35.0 | 39.0 | 91.0 | 94.0 | 98.0 | 118.0 | 126.0 | 130.0 | 43.0 | 47.0 | 63.0 | 25.0x16.0 | 63.0x35.0 | 71.0x28.0 | 94.0x26.0 | 94.0x31.0 | 94.0x47.0 | 96.0x24.0 | 102.0x28.0 | 138.0x91.0 | 154.0x106.0 | 185.0x138.0 | DRILL CHART: TOP to BOTTOM | ALL UNITS ARE IN MILS | PLATED | NON-PLATED | QTY | 41 | 5961 | 19 | 18 | 15 | 8 | 4 | 1 | 2 | 9 | 3 | 24
